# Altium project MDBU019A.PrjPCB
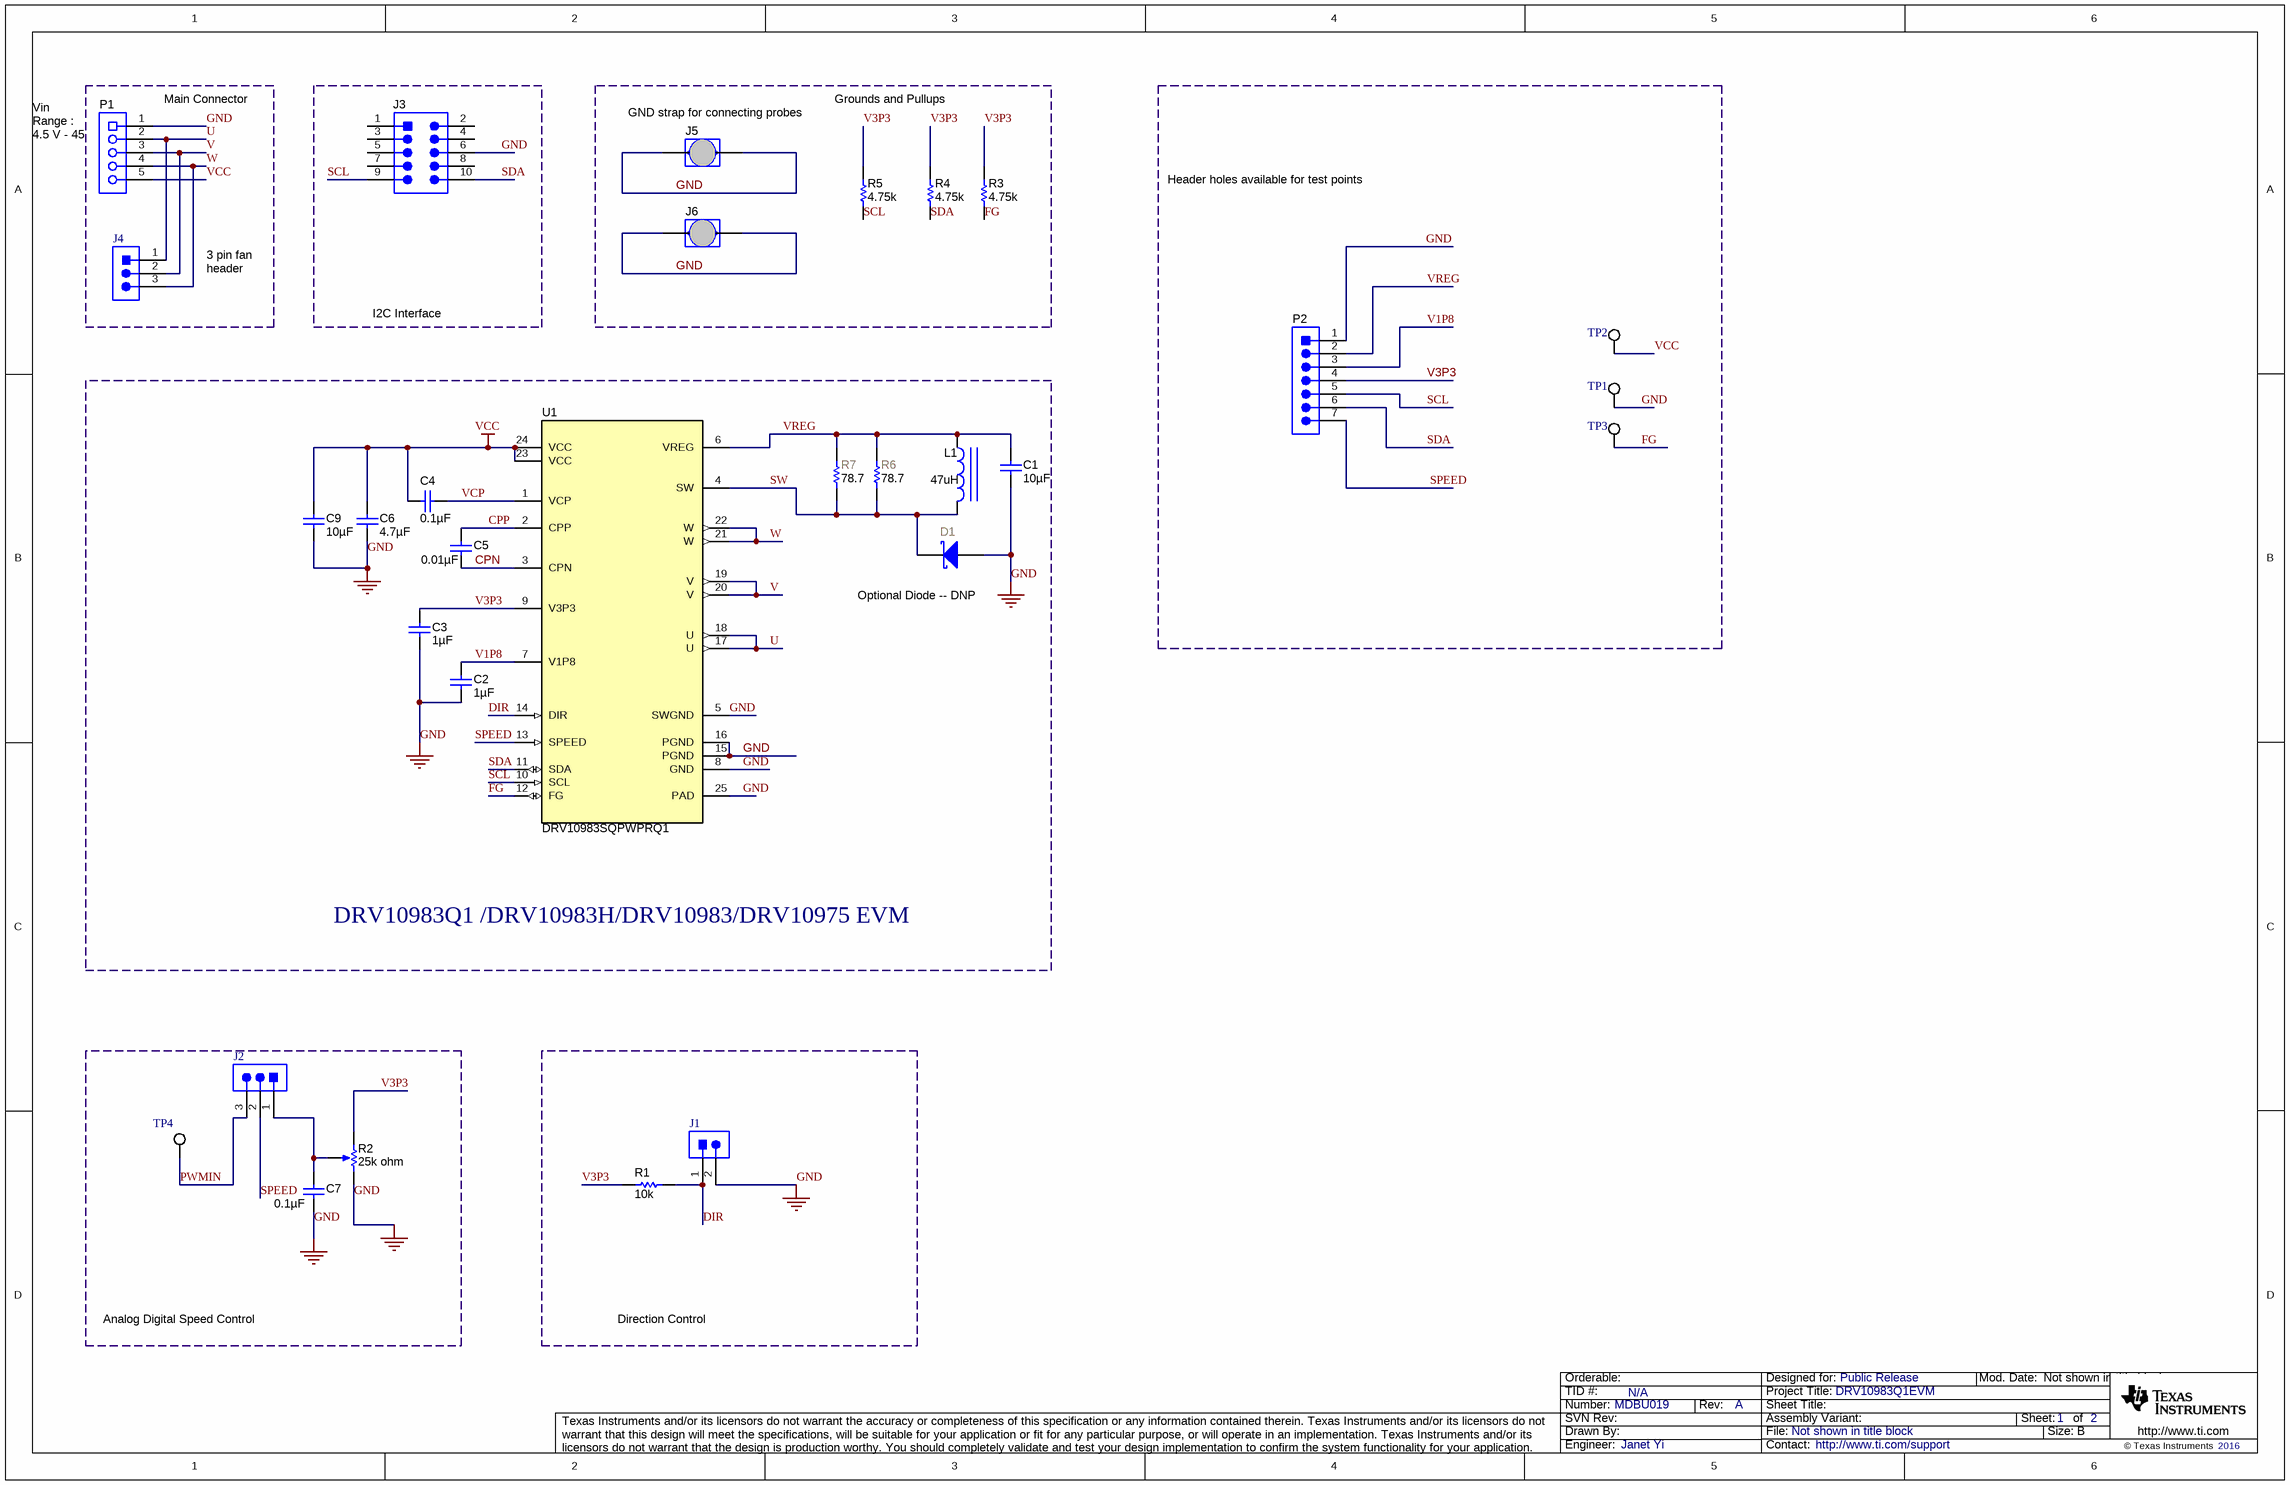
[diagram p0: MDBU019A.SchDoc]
TID: N/A; TechSupport: http://www.ti.com/support; SCH_Rev: A; PRJ_Title: DRV10983Q1EVM; PRJ_Number: MDBU019; PRJ_Engineer: Janet Yi; PRJ_Customer: Public Release; PCB_Rev: A; PCB_Layout: Janet Yi; Orderable: DRV10983QEVM; ITD: N/A; CopyrightYear: 2016
2 sheets, 50 parts. Net scope: global (net labels, ports and power ports of the same name join across sheets).
Board file: MDBU019A.PcbDoc
Sheets:
  MDBU019A.SchDoc
  MDBU019A_EVM_Hardware.SchDoc

## Sheet MDBU019A.SchDoc
size 431 x 279 mm; Date: Not shown in title block; ApprovedBy: Not shown in title block; CheckedBy: Not shown in title block; Author: Not shown in title block; CompanyName: Not shown in title block; Engineer: Not shown in title block; Organization: Not shown in title block; Address1: Not shown in title block; Address2: Not shown in title block; Address3: Not shown in title block; Address4: Not shown in title block; DocumentNumber: 1; Revision: Use project parameter SCH_Rev; SheetNumber: 1; SheetTotal: 2; PageSetup: Record=PageOptions¦CenterHorizontal=True¦CenterVertical=True¦PrintScale=1.00¦XCorrection=1.00¦YCorrection=1.00¦PrintKind=0¦BorderSize=5000000¦LeftOffset=0¦BottomOffset=0¦Orientation=2¦PaperLength=1000¦PaperWidth=1000¦Scale=100¦PaperSource=15¦PrintQuality=600¦MediaType=1¦DitherType=10¦PaperKind=Letter¦PrintScaleMode=1

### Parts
C1  ValueDisplayed: 10µF  [0603L]  (hidden comment: C1608X5R1A106M080AC)
C2  ValueDisplayed: 1µF  [0603L]  (hidden comment: C1608X5R1E105K080AC)
C3  ValueDisplayed: 1µF  [0603L]  (hidden comment: C1608X5R1E105K080AC)
C4  ValueDisplayed: 0.1µF  [0603]  (hidden comment: 06035C104KAT2A)
C5  ValueDisplayed: 0.01µF  [0603]  (hidden comment: 06031C103KAT2A)
C6  ValueDisplayed: 4.7µF  [0805_HV]  (hidden comment: C2012X5R1H475K125AB)
C7  ValueDisplayed: 0.1µF  [0603]  (hidden comment: 06035C104KAT2A)
C9  ValueDisplayed: 10µF  [1206_180]  (hidden comment: C3216X5R1H106K160AB)
D1  VS-10BQ030HM3/5BT  [SMB]  (value not drawn)
J1  90120-0122  [CONN_90120-0122]  (value not drawn)
J2  PEC03SAAN  [CONN_PEC03SAAN]  (value not drawn)
J3  5103308-1  [CONN_5103308-1]  (value not drawn)
J4  PEC03SAAN  [CONN_PEC03SAAN]  (value not drawn)
J5  D3082-05  [Harwin_D3082-05]  (value not drawn)
J6  D3082-05  [Harwin_D3082-05]  (value not drawn)
L1  value 47uH  [DR74]  (hidden comment: DR74-470-R)
P1  ED120/5DS  [On-Shore_ED120_5DS]  (value not drawn)
P2  TSW-107-07-G-S  [TSW-107-07-G-S]  (value not drawn)
R1  value 10k  [0603]  (hidden comment: CRCW060310K0JNEA)
R2  value 25k ohm  [CTS_296X]  (hidden comment: 296XD253B1N)
R3  value 4.75k  [0603]  (hidden comment: CRCW06034K75FKEA)
R4  value 4.75k  [0603]  (hidden comment: CRCW06034K75FKEA)
R5  value 4.75k  [0603]  (hidden comment: CRCW06034K75FKEA)
R6  value 78.7  [0805_HV]  (hidden comment: CRCW080578R7FKEA)
R7  value 78.7  [0805_HV]  (hidden comment: CRCW080578R7FKEA)
TP1  5016  [Testpoint_Keystone_Compact]  (value not drawn)
TP2  5016  [Testpoint_Keystone_Compact]  (value not drawn)
TP3  5016  [Testpoint_Keystone_Compact]  (value not drawn)
TP4  5016  [Testpoint_Keystone_Compact]  (value not drawn)
U1  DRV10983SQPWPRQ1  [PWP0024B_N]

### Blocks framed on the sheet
Main Connector: J4 P1
I2C Interface: J3
Header holes available for test points: P2 TP1-TP3
DRV10983Q1 /DRV10983H/DRV10983/DRV10975 EVM: C1-C6 C9 D1 L1 R6 R7 U1
Analog Digital Speed Control: C7 J2 R2 TP4
Direction Control: J1 R1

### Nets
GND: C1.2 C2.1 C3.1 C6.1 C7.2 C9.2 D1.2(A) J1.2 J3.6 J5.1 J5.2 J6.1 J6.2 P1.1 P2.1 R2.3(CW) TP1.1 U1.5(SWGND) U1.8(GND) U1.15(PGND) U1.16(PGND) U1.25(PAD)
VCC: C4.1 C6.2 C9.1 P1.5 TP2.1 U1.23(VCC) U1.24(VCC)
CPN: C5.1 U1.3(CPN)
CPP: C5.2 U1.2(CPP)
DIR: J1.1 R1.2 U1.14(DIR)
FG: R3.2 TP3.1 U1.12(FG)
PWMIN: J2.3 TP4.1
SCL: J3.9 P2.5 R5.2 U1.10(SCL)
SDA: J3.10 P2.6 R4.2 U1.11(SDA)
SPEED: J2.2 P2.7 U1.13(SPEED)
SW: D1.1(K) L1.2 R6.2 R7.2 U1.4(SW)
U: J4.1 P1.2 U1.17(U) U1.18(U)
V: J4.2 P1.3 U1.19(V) U1.20(V)
V1P8: C2.2 P2.3 U1.7(V1P8)
V3P3: C3.2 P2.4 R1.1 R2.1(CCW) R3.1 R4.1 R5.1 U1.9(V3P3)
VCP: C4.2 U1.1(VCP)
VREG: C1.1 L1.1 P2.2 R6.1 R7.1 U1.6(VREG)
W: J4.3 P1.4 U1.21(W) U1.22(W)
NetC7_1: C7.1 J2.1 R2.2(WIPER)

Not connected (* = marked no-connect by the designer): J3 1 2 3 4 5 7 8

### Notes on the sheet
- Grounds and Pullups
- (near P1) Vin Range : 4.5 V - 45 V
- (near J5) GND strap for connecting probes
- 3 pin fan header
- (near D1) Optional Diode -- DNP

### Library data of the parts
C1 = C1608X5R1A106M080AC: CAP, CERM, 10 µF, 10 V, +/- 20%, X5R, 0603; Manufacturer: TDK; Value: 10uF; Polarized: N; CompType: Capacitor; U/M: EA; Cap_F: 0.00001; Tolerance_%: 20; ESR_ohm: 0.0078; Value1: 0.0078 ohm; VDC_V: 10; Value2: 10V; IRMS_A: 1.85; TaMin_C: -55; TaMax_C: 85; Cap_Case: 0603; SizeArea_mm2: 1.28; SizeAreaWB_mm2: 4.68; SizeX_mm: 1.6; SizeY_mm: 0.8; SizeZ_mm: 1; AEC Category: Q200; Green_Lifecycle: Active; Green_REACh: Passed
C2 C3 = C1608X5R1E105K080AC: CAP, CERM, 1 µF, 25 V, +/- 10%, X5R, 0603; Manufacturer: TDK; Value: 1uF; Polarized: N; CompType: Capacitor; U/M: EA; Cap_F: 0.000001; Tolerance_%: 10; Value1: Unknown; VDC_V: 25; Value2: 25V; TaMin_C: -55; TaMax_C: 85; Cap_Case: 0603; SizeArea_mm2: 1.28; SizeAreaWB_mm2: 4.68; SizeX_mm: 1.6; SizeY_mm: 0.8; SizeZ_mm: 1; AEC Category: Q200; Green_Lifecycle: Active; Green_REACh: Passed
C4 C7 = 06035C104KAT2A: CAP, CERM, 0.1 µF, 50 V, +/- 10%, X7R, 0603; Manufacturer: AVX; Value: 0.1uF; Polarized: N; CompType: Capacitor; U/M: EA; Cap_F: 0.0000001; Tolerance_%: 10; Value1: Unknown; VDC_V: 50; Value2: 50V; TaMin_C: -55; TaMax_C: 125; SizeArea_mm2: 1.28; SizeAreaWB_mm2: 4.68; SizeX_mm: 1.6; SizeY_mm: 0.8; SizeZ_mm: 1; AEC Category: Q200; Green_Lifecycle: Active; Green_REACh: Passed
C5 = 06031C103KAT2A: CAP, CERM, 0.01 µF, 100 V, +/- 10%, X7R, 0603; Manufacturer: AVX; Value: 0.01uF; Polarized: N; CompType: Capacitor; U/M: EA; Cap_F: 0.00000001; Tolerance_%: 10; ESR_ohm: 0.098; Value1: 0.098 ohm; VDC_V: 100; Value2: 100V; TaMin_C: -55; TaMax_C: 125; SizeArea_mm2: 1.28; SizeAreaWB_mm2: 4.68; SizeX_mm: 1.6; SizeY_mm: 0.8; SizeZ_mm: 1; AEC Category: Q200; Green_Lifecycle: Active; Green_REACh: Passed
C6 = C2012X5R1H475K125AB: CAP, CERM, 4.7 µF, 50 V, +/- 10%, X5R, 0805; Manufacturer: TDK; Value: 4.7uF; Polarized: N; CompType: Capacitor; U/M: EA; Cap_F: 0.0000047; Tolerance_%: 10; ESR_ohm: 0.002346; Value1: 0.002346 ohm; VDC_V: 50; Value2: 50V; IRMS_A: 4.26021; TaMin_C: -55; TaMax_C: 85; Cap_Case: 0805; SizeArea_mm2: 2.5; SizeAreaWB_mm2: 6.75; SizeX_mm: 2; SizeY_mm: 1.25; SizeZ_mm: 1.45; AEC Category: Q200; Green_Lifecycle: Active; Green_REACh: Passed
C9 = C3216X5R1H106K160AB: CAP, CERM, 10 µF, 50 V, +/- 10%, X5R, 1206; Manufacturer: TDK; Polarized: N; CompType: Capacitor; Value: 10uF; U/M: EA; Cap_F: 0.00001; Tolerance_%: 10; ESR_ohm: 0.002229; Value1: 0.002229 ohm; VDC_V: 50; Value2: 50V; IRMS_A: 4.85932; TaMin_C: -55; TaMax_C: 85; Cap_Case: 1206; SizeArea_mm2: 5.12; SizeAreaWB_mm2: 10.92; SizeX_mm: 3.2; SizeY_mm: 1.6; SizeZ_mm: 1.8; AEC Category: Q200; Green_Lifecycle: Active; Green_REACh: Passed
D1 = VS-10BQ030HM3/5BT: Diode, Schottky, 30 V, 1 A, AEC-Q101, SMB; Manufacturer: Vishay-Semiconductor; U/M: EA; Vf_V: 0.42; Value: 30V; Value1: 1A; Value2: 0.42V; Io_A: 1; Vr_V: 30; TJmax_C: 150; SizeAreaWB_mm2: 44.156; SizeArea_mm2: 21.336; SizeX_mm: 5.6; SizeY_mm: 3.81; SizeZ_mm: 2.6; AEC Category: Q101; AEC Qualified: Y; Green_Lifecycle: Not Set; Green_REACh: Incomplete
J1 = 90120-0122: Header, 100mil, 2x1, Tin, TH; Manufacturer: Molex; SymbolCreator: a0412235
J2 J4 = PEC03SAAN: Header, 100mil, 3x1, Tin, TH; Manufacturer: Sullins Connector Solutions; SymbolCreator: a0412235; Pitch_mm: 2.54; Gender: Male; Shrouded: N; Row_Count: 1; Current_A: 3; Voltage_V: 1800; Cert_UL: Y; Green_Lifecycle: Not Set; Green_REACh: Incomplete
J3 = 5103308-1: Header (shrouded), 100mil, 5x2, Gold, TH; Manufacturer: TE Connectivity; SymbolCreator: a0412235; Green_Lifecycle: Active; Green_REACh: Passed
J5 J6 = D3082-05: 1mm Uninsulated Shorting Plug, 10.16mm spacing, TH; Manufacturer: Harwin; SymbolCreator: a0799628; CompType: Jumper Wire; Green_Lifecycle: Active; Green_REACh: Passed
L1 = DR74-470-R: Inductor, Shielded Drum Core, Ferrite, 47 µH, 1.15 A, 0.216 ohm, SMD; Manufacturer: Coiltronics; Ind_H: 47.0E-6; ValueDisplayed: 47µH; Imax_A: 1.15; Irms: 1.15A @ 40C rise; Isat: 1.41A @ 30% inductance drop; DCR_ohm: 0.216; Value2: 1.15A; SizeAreaWB_mm2: 92.16; SizeArea_mm2: 57.76; SizeX_mm: 7.6; SizeZ_mm: 4.35; AEC Category: Q200
P1 = ED120/5DS: Terminal Block, 5.08 mm, 5x1, Brass, TH; Manufacturer: On-Shore Technology; SymbolCreator: a0412235; Pitch_mm: 5.08; Gender: Female; Shrouded: N; Row_Count: 1; Current_A: 15; Voltage_V: 300; Cert_CULUS: Y
P2 = TSW-107-07-G-S: Header, 100mil, 7x1, Gold, TH; Manufacturer: Samtec; SymbolCreator: a0411947; Pitch_mm: 2.54; Gender: Male; Shrouded: N; Row_Count: 1; Current_A: 6.3; Voltage_V: 550; Cert_CSA: Y
R1 = CRCW060310K0JNEA: RES, 10 k, 5%, 0.1 W, 0603; Manufacturer: Vishay-Dale; CompType: Resistor; Res_ohm: 10000; Value_Code: 10k0; Tolerance_%: 5; Power_W: 0.1; Value2: 0.1W; VDC_V: 75; TempCo: 200 ppm/C; EIA_Code: E24; U/M: EA; SizeArea_mm2: 1.28; SizeX_mm: 1.6; SizeY_mm: 0.8; SizeZ_mm: 1; AEC Category: Q200; Green_Lifecycle: Active; Green_REACh: Passed
R2 = 296XD253B1N: Trimmer, 25k ohm, 0.15W, TH; Manufacturer: CTS Electrocomponents; Sim Note: Enter the Resistance value and the set point into parameter fields.; SymbolCreator: a0412235
R3-R5 = CRCW06034K75FKEA: RES, 4.75 k, 1%, 0.1 W, 0603; Manufacturer: Vishay-Dale; CompType: Resistor; Res_ohm: 4750; Value_Code: 4k75; Tolerance_%: 1; Power_W: 0.1; Value2: 0.1W; VDC_V: 75; TempCo: 100 ppm/C; EIA_Code: E96; U/M: EA; SizeArea_mm2: 1.28; SizeX_mm: 1.6; SizeY_mm: 0.8; AEC Category: Q200; Green_Lifecycle: Active; Green_REACh: Passed
R6 R7 = CRCW080578R7FKEA: RES, 78.7, 1%, 0.125 W, 0805; Manufacturer: Vishay-Dale; CompType: Resistor; Value_Code: 78R7; Tolerance_%: 1; Power_W: 0.125; Value2: 0.125W; VDC_V: 150; TempCo: 100 ppm/C; EIA_Code: E96; U/M: EA; SizeArea_mm2: 2.5; SizeX_mm: 2; SizeY_mm: 1.25; SizeZ_mm: 1.45; AEC Category: Q200
TP1-TP4 = 5016: Test Point, Compact, SMT; Manufacturer: Keystone; CompType: Test Point Loop
U1 = DRV10983SQPWPRQ1: Industrial, Three-Phase, Sensorless BLDC Motor Driver, PWP0024B (TSSOP-24); Manufacturer: Texas Instruments; SymbolCreator: a0411947; SizeArea_mm2: 49.92; SizeAreaWB_mm2: 82.32; SizeX_mm: 6.4; SizeY_mm: 7.8; SizeZ_mm: 1.2; CompType: IC; U/M: EA

## Sheet MDBU019A_EVM_Hardware.SchDoc
size 431 x 279 mm; Date: Not shown in title block; ApprovedBy: Not shown in title block; CheckedBy: Not shown in title block; Author: Not shown in title block; CompanyName: Not shown in title block; Engineer: Not shown in title block; Organization: Not shown in title block; Address1: Not shown in title block; Address2: Not shown in title block; Address3: Not shown in title block; Address4: Not shown in title block; DocumentNumber: 2; Revision: Use project parameter SCH_Rev; SheetNumber: 1; SheetTotal: 2; PageSetup: Record=PageOptions¦CenterHorizontal=True¦CenterVertical=True¦PrintScale=1.00¦XCorrection=1.00¦YCorrection=1.00¦PrintKind=0¦BorderSize=5000000¦LeftOffset=0¦BottomOffset=0¦Orientation=2¦PaperLength=1000¦PaperWidth=1000¦Scale=100¦PaperSource=15¦PrintQuality=600¦MediaType=1¦DitherType=10¦PaperKind=Letter¦PrintScaleMode=1
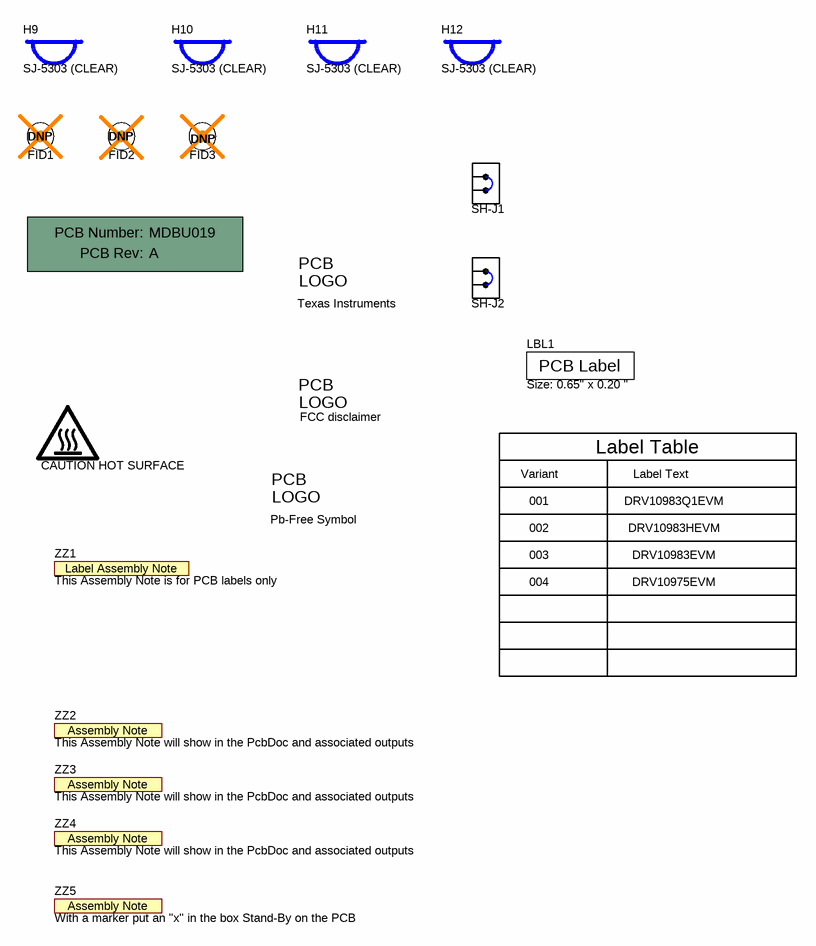
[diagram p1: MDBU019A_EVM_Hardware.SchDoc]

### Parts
!PCB  Printed Circuit Board  (value not drawn)  (mechanical)
FID1  Fiducial  [Fiducial10-30]  (value not drawn)
FID2  Fiducial  [Fiducial10-30]  (value not drawn)
FID3  Fiducial  [Fiducial10-30]  (value not drawn)
H9  SJ-5303 (CLEAR)  [Bumpon_SJ5003Transparent]
H10  SJ-5303 (CLEAR)  [Bumpon_SJ5003Transparent]
H11  SJ-5303 (CLEAR)  [Bumpon_SJ5003Transparent]
H12  SJ-5303 (CLEAR)  [Bumpon_SJ5003Transparent]
LBL1  Size: 0.65" x 0.20 "  [Label_650x200]
Logo1  Texas Instruments  [TI_Stacked_Overlay_Small]  (no BOM)
Logo2  Pb-Free Symbol  [Pb-Free_Overlay_Small]  (no BOM)
Logo3  FCC disclaimer  [FCC_disclaimer]  (no BOM)
LOGO4  CAUTION HOT SURFACE  [IEC_HotSurface_Small]  (no BOM)
SH-J1  969102-0000-DA  [SNT-100-BK-G]  (value not drawn)
SH-J2  969102-0000-DA  [SNT-100-BK-G]  (value not drawn)
ZZ1  This Assembly Note is for PCB labels only  [AssemblyNoteLabel]  (no BOM)
ZZ2  This Assembly Note will show in the PcbDoc and associated outputs  [AssemblyNote]  (no BOM)
ZZ3  This Assembly Note will show in the PcbDoc and associated outputs  [AssemblyNote]  (no BOM)
ZZ4  This Assembly Note will show in the PcbDoc and associated outputs  [AssemblyNote]  (no BOM)
ZZ5  With a marker put an "x" in the box Stand-By on the PCB  [AssemblyNote]  (no BOM)

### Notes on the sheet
- (near FID1) DNP
- (near FID2) DNP
- (near FID3) DNP
- Variant
- Label Table
- Label Text
- 001
- 002
- 003
- DRV10983Q1EVM
- DRV10983HEVM
- DRV10983EVM
- 004
- DRV10975EVM

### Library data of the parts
!PCB = PCB: Manufacturer: Any; PartNumber: MDBU019; SymbolCreator: a0412235
FID1-FID3 = Fiducial: Fiducial mark.  There is nothing to buy or mount.; SymbolCreator: codlsc
H9-H12 = SJ-5303 (CLEAR): Bumpon, Hemisphere, 0.44 X 0.20, Clear; Manufacturer: 3M; SymbolCreator: a0412235; Green_Lifecycle: Active; Green_REACh: Passed
LBL1 = THT-14-423-10: Thermal Transfer Printable Labels, 0.650" W x 0.200" H - 10,000 per roll; Manufacturer: Brady; SymbolCreator: a0412235; CompType: Label; Green_Lifecycle: Not Set; Green_REACh: Incomplete
Logo1 = TI_Logo: Texas Instrument Corporate Signature; SymbolCreator: a0412235
Logo2 = Pb-Free: SymbolCreator: a0412235
Logo3 = FCC_disclaimer: SymbolCreator: a0412235
LOGO4 = IEC_HotSurface: IEC 61010-1 Hot Surface Warning; SymbolCreator: a0412235
SH-J1 SH-J2 = 969102-0000-DA: Shunt, 100mil, Gold plated, Black; Manufacturer: 3M; Alternate Manufacturer: Samtec; Value: 1x2; Note: You can "mate" this to a header by matching the designator.  i.e. use SH-J3 for header J3; Green_Lifecycle: Active; Green_REACh: Passed
ZZ1 = AssemblyNoteLabel: SymbolCreator: a0412235
ZZ2-ZZ4 = AssemblyNote: SymbolCreator: codlsc
ZZ5 = AssemblyNote: This Assembly Note will show in the PcbDoc and associated outputs; SymbolCreator: codlsc

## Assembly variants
001: not fitted C6 D1 FID1 FID2 FID3 P2 R6 R7
002: not fitted C6 D1 FID1 FID2 FID3 P2 R6 R7; alternate parts U1 -> DRV10983HPWP
003: not fitted C6 D1 FID1 FID2 FID3 P2 R6 R7; alternate parts U1 -> DRV10983PWP, C5 -> 06035C104KAT2A
004: not fitted C6 D1 FID1 FID2 FID3 P2 R6 R7; alternate parts U1 -> DRV10975PWPR, C5 -> 06035C104KAT2A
